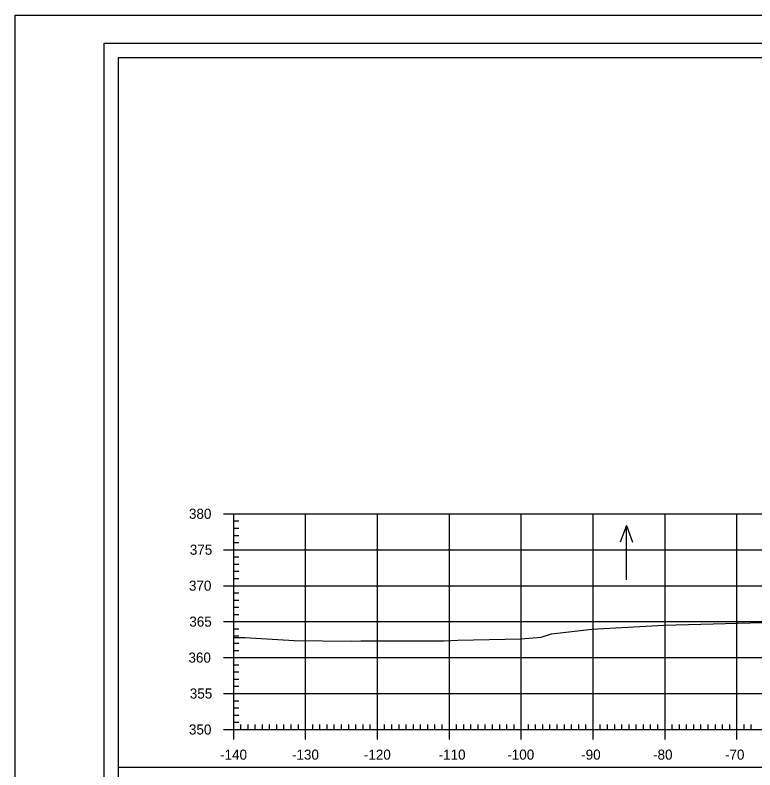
# Model space of a CAD drawing. Extents: x 1368910 to 1369601, y 380116 to 380950.
# Drawn here: x 1368909.8 to 1369012.7, y 380418.8 to 380523.8 of the extents above; entities that cross this region are included whole.
import ezdxf

# ---------------------------------------------------------------- set-up
doc = ezdxf.new("R2010")
doc.units = 0
for name, color, linetype in [('R_Axis', 7, 'Continuous'), ('R_Axis Annot', 7, 'Continuous'), ('R_Border', 7, 'Continuous'), ('R_Exist Surface', 7, 'Continuous'), ('R_Grid', 7, 'Continuous'), ('R_No Plot', 7, 'Continuous'), ('R_Water Annot', 7, 'Continuous')]:
    doc.layers.add(name, color=color, linetype=linetype)

msp = doc.modelspace()

# ---------------------------------------------------------------- linework, layer by layer
at = {"layer": 'R_Axis'}
for p, q in [((1368938.84, 380454.42), (1368941.64, 380454.42)), ((1368940.24, 380424.42), (1368940.24, 380454.42)), ((1368940.24, 380453.42), (1368940.94, 380453.42)), ((1368940.24, 380452.42), (1368940.94, 380452.42)), ((1368940.24, 380451.42), (1368940.94, 380451.42)), ((1368940.24, 380450.42), (1368940.94, 380450.42)), ((1368938.84, 380449.42), (1368941.64, 380449.42)), ((1368940.24, 380448.42), (1368940.94, 380448.42)), ((1368940.24, 380447.42), (1368940.94, 380447.42)), ((1368940.24, 380446.42), (1368940.94, 380446.42)), ((1368940.24, 380445.42), (1368940.94, 380445.42)), ((1368938.84, 380444.42), (1368941.64, 380444.42)), ((1368940.24, 380443.42), (1368940.94, 380443.42)), ((1368940.24, 380442.42), (1368940.94, 380442.42)), ((1368940.24, 380441.42), (1368940.94, 380441.42)), ((1368940.24, 380440.42), (1368940.94, 380440.42)), ((1368938.84, 380439.42), (1368941.64, 380439.42)), ((1368940.24, 380438.42), (1368940.94, 380438.42)), ((1368940.24, 380437.42), (1368940.94, 380437.42)), ((1368940.24, 380436.42), (1368940.94, 380436.42)), ((1368940.24, 380435.42), (1368940.94, 380435.42)), ((1368938.84, 380434.42), (1368941.64, 380434.42)), ((1368940.24, 380433.42), (1368940.94, 380433.42)), ((1368940.24, 380432.42), (1368940.94, 380432.42)), ((1368940.24, 380431.42), (1368940.94, 380431.42)), ((1368940.24, 380430.42), (1368940.94, 380430.42)), ((1368938.84, 380429.42), (1368941.64, 380429.42)), ((1368940.24, 380428.42), (1368940.94, 380428.42)), ((1368940.24, 380427.42), (1368940.94, 380427.42)), ((1368940.24, 380426.42), (1368940.94, 380426.42)), ((1368940.24, 380423.02), (1368940.24, 380425.82)), ((1368950.24, 380423.02), (1368950.24, 380425.82)), ((1368960.24, 380423.02), (1368960.24, 380425.82)), ((1368970.24, 380423.02), (1368970.24, 380425.82)), ((1368980.24, 380423.02), (1368980.24, 380425.82)), ((1368990.24, 380423.02), (1368990.24, 380425.82)), ((1369000.24, 380423.02), (1369000.24, 380425.82)), ((1369010.24, 380423.02), (1369010.24, 380425.82)), ((1368940.24, 380425.42), (1368940.94, 380425.42)), ((1368941.24, 380424.42), (1368941.24, 380425.12)), ((1368942.24, 380424.42), (1368942.24, 380425.12)), ((1368943.24, 380424.42), (1368943.24, 380425.12)), ((1368944.24, 380424.42), (1368944.24, 380425.12)), ((1368945.24, 380424.42), (1368945.24, 380425.12)), ((1368946.24, 380424.42), (1368946.24, 380425.12)), ((1368947.24, 380424.42), (1368947.24, 380425.12)), ((1368948.24, 380424.42), (1368948.24, 380425.12)), ((1368949.24, 380424.42), (1368949.24, 380425.12)), ((1368951.24, 380424.42), (1368951.24, 380425.12)), ((1368952.24, 380424.42), (1368952.24, 380425.12)), ((1368953.24, 380424.42), (1368953.24, 380425.12)), ((1368954.24, 380424.42), (1368954.24, 380425.12)), ((1368955.24, 380424.42), (1368955.24, 380425.12)), ((1368956.24, 380424.42), (1368956.24, 380425.12)), ((1368957.24, 380424.42), (1368957.24, 380425.12)), ((1368958.24, 380424.42), (1368958.24, 380425.12)), ((1368959.24, 380424.42), (1368959.24, 380425.12)), ((1368961.24, 380424.42), (1368961.24, 380425.12)), ((1368962.24, 380424.42), (1368962.24, 380425.12)), ((1368963.24, 380424.42), (1368963.24, 380425.12)), ((1368964.24, 380424.42), (1368964.24, 380425.12)), ((1368965.24, 380424.42), (1368965.24, 380425.12)), ((1368966.24, 380424.42), (1368966.24, 380425.12)), ((1368967.24, 380424.42), (1368967.24, 380425.12)), ((1368968.24, 380424.42), (1368968.24, 380425.12)), ((1368969.24, 380424.42), (1368969.24, 380425.12)), ((1368971.24, 380424.42), (1368971.24, 380425.12)), ((1368972.24, 380424.42), (1368972.24, 380425.12)), ((1368973.24, 380424.42), (1368973.24, 380425.12)), ((1368974.24, 380424.42), (1368974.24, 380425.12)), ((1368975.24, 380424.42), (1368975.24, 380425.12)), ((1368976.24, 380424.42), (1368976.24, 380425.12)), ((1368977.24, 380424.42), (1368977.24, 380425.12)), ((1368978.24, 380424.42), (1368978.24, 380425.12)), ((1368979.24, 380424.42), (1368979.24, 380425.12)), ((1368981.24, 380424.42), (1368981.24, 380425.12)), ((1368982.24, 380424.42), (1368982.24, 380425.12)), ((1368983.24, 380424.42), (1368983.24, 380425.12)), ((1368984.24, 380424.42), (1368984.24, 380425.12)), ((1368985.24, 380424.42), (1368985.24, 380425.12)), ((1368986.24, 380424.42), (1368986.24, 380425.12)), ((1368987.24, 380424.42), (1368987.24, 380425.12)), ((1368988.24, 380424.42), (1368988.24, 380425.12)), ((1368989.24, 380424.42), (1368989.24, 380425.12)), ((1368991.24, 380424.42), (1368991.24, 380425.12)), ((1368992.24, 380424.42), (1368992.24, 380425.12)), ((1368993.24, 380424.42), (1368993.24, 380425.12)), ((1368994.24, 380424.42), (1368994.24, 380425.12)), ((1368995.24, 380424.42), (1368995.24, 380425.12)), ((1368996.24, 380424.42), (1368996.24, 380425.12)), ((1368997.24, 380424.42), (1368997.24, 380425.12)), ((1368998.24, 380424.42), (1368998.24, 380425.12)), ((1368999.24, 380424.42), (1368999.24, 380425.12)), ((1369001.24, 380424.42), (1369001.24, 380425.12)), ((1369002.24, 380424.42), (1369002.24, 380425.12)), ((1369003.24, 380424.42), (1369003.24, 380425.12)), ((1369004.24, 380424.42), (1369004.24, 380425.12)), ((1369005.24, 380424.42), (1369005.24, 380425.12)), ((1369006.24, 380424.42), (1369006.24, 380425.12)), ((1369007.24, 380424.42), (1369007.24, 380425.12)), ((1369008.24, 380424.42), (1369008.24, 380425.12)), ((1369009.24, 380424.42), (1369009.24, 380425.12)), ((1369011.24, 380424.42), (1369011.24, 380425.12)), ((1369012.24, 380424.42), (1369012.24, 380425.12)), ((1368938.84, 380424.42), (1368941.64, 380424.42)), ((1368940.24, 380424.42), (1369220.24, 380424.42))]:
    msp.add_line(p, q, dxfattribs=at)
at = {"layer": 'R_Border'}
for p, q in [((1368922.24, 380519.88), (1369238.42, 380519.88)), ((1368922.24, 380314.42), (1368922.24, 380519.88))]:
    msp.add_line(p, q, dxfattribs=at)
at = {"layer": 'R_Exist Surface'}
msp.add_lwpolyline([(1368940.24, 380437.21), (1368941.81, 380437.23), (1368948.65, 380436.79), (1368956.57, 380436.72), (1368957.91, 380436.75), (1368968.8, 380436.75), (1368969.49, 380436.76), (1368971.4, 380436.82), (1368980.2, 380437.04), (1368982.99, 380437.27), (1368984.43, 380437.73), (1368990.07, 380438.35), (1369000.06, 380438.92), (1369012.08, 380439.25), (1369013.88, 380439.3)], dxfattribs=at)
at = {"layer": 'R_Grid'}
for p, q in [((1368940.24, 380454.42), (1369220.24, 380454.42)), ((1368940.24, 380424.42), (1368940.24, 380454.42)), ((1368950.24, 380424.42), (1368950.24, 380454.42)), ((1368960.24, 380424.42), (1368960.24, 380454.42)), ((1368970.24, 380424.42), (1368970.24, 380454.42)), ((1368980.24, 380424.42), (1368980.24, 380454.42)), ((1368990.24, 380424.42), (1368990.24, 380454.42)), ((1369000.24, 380424.42), (1369000.24, 380454.42)), ((1369010.24, 380424.42), (1369010.24, 380454.42)), ((1368940.24, 380449.42), (1369220.24, 380449.42)), ((1368940.24, 380444.42), (1369220.24, 380444.42)), ((1368940.24, 380439.42), (1369220.24, 380439.42)), ((1368940.24, 380434.42), (1369220.24, 380434.42)), ((1368940.24, 380429.42), (1369220.24, 380429.42)), ((1368940.24, 380424.42), (1369220.24, 380424.42))]:
    msp.add_line(p, q, dxfattribs=at)
at = {"layer": 'R_No Plot'}
for points in [[(1368909.84, 380523.78), (1369243.18, 380523.78), (1369243.18, 380310.44), (1368909.84, 380310.44)], [(1369236.42, 380419.15), (1368924.24, 380419.15), (1368924.24, 380517.88), (1369173.78, 380517.88), (1369173.78, 380508), (1369191.32, 380508), (1369215.42, 380508), (1369215.42, 380485.67), (1369236.42, 380485.67)], [(1368924.24, 380517.88), (1369173.78, 380517.88), (1369173.78, 380508), (1369191.32, 380508), (1369215.42, 380508), (1369215.42, 380485.67), (1369236.42, 380485.67), (1369236.42, 380316.42), (1368924.24, 380316.42)]]:
    msp.add_lwpolyline(points, close=True, dxfattribs=at)
at = {"layer": 'R_Water Annot'}
for p, q in [((1368994.86, 380452.77), (1368994.02, 380450.46)), ((1368994.86, 380445.23), (1368994.86, 380452.77)), ((1368994.86, 380452.77), (1368995.7, 380450.46))]:
    msp.add_line(p, q, dxfattribs=at)

# ---------------------------------------------------------------- texts
at = {"layer": 'R_Axis Annot'}
for s, p in [('380', (1368934.02, 380453.72)), ('375', (1368934.14, 380448.72)), ('370', (1368934.02, 380443.72)), ('365', (1368934.07, 380438.72)), ('360', (1368933.95, 380433.72)), ('355', (1368934.14, 380428.72)), ('350', (1368934.02, 380423.72)), ('-140', (1368938.35, 380420.22)), ('-130', (1368948.35, 380420.22)), ('-120', (1368958.35, 380420.22)), ('-110', (1368968.75, 380420.22)), ('-100', (1368978.3, 380420.22)), ('-90', (1368988.58, 380420.22)), ('-80', (1368998.58, 380420.22)), ('-70', (1369008.58, 380420.22))]:
    msp.add_text(s, height=1.4, dxfattribs=at).set_placement(p)

doc.saveas('drawing.dxf')
